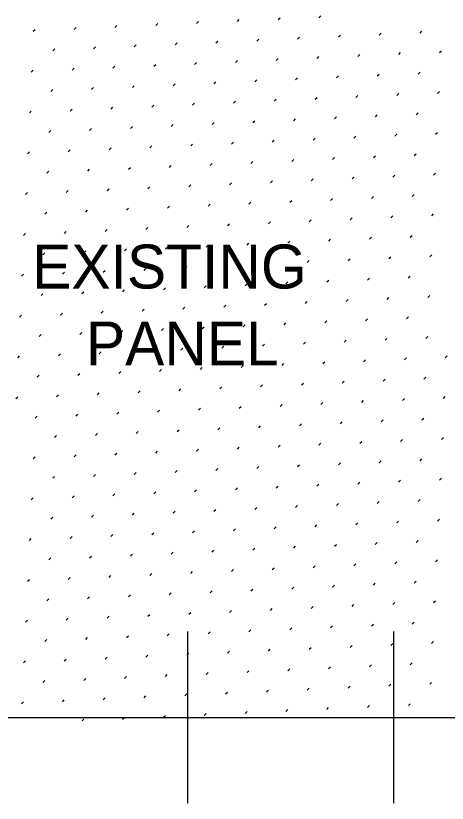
# Model space of a CAD drawing. Extents: x 49991.4 to 50021, y 49987.6 to 50011.4.
# Drawn here: x 50002.935 to 50003.72, y 49996.134 to 49997.567 of the extents above; entities that cross this region are included whole.
import ezdxf

# ---------------------------------------------------------------- set-up
doc = ezdxf.new("R2010")
doc.units = 0
for name, color, linetype in [('Level 1', 7, 'Continuous'), ('Level 10', 7, 'Continuous'), ('Level 2', 7, 'Continuous'), ('Level 4', 7, 'Continuous')]:
    doc.layers.add(name, color=color, linetype=linetype)

msp = doc.modelspace()

# ---------------------------------------------------------------- linework, layer by layer
at = {"layer": 'Level 1'}
msp.add_line((50002.3098, 49996.2901), (50007.9348, 49996.2901), dxfattribs=at)
at = {"layer": 'Level 10'}
for p, q in [((50003.4125, 49997.5595), (50003.416, 49997.5631)), ((50003.4867, 49997.5631), (50003.4903, 49997.5666)), ((50003.1155, 49997.5454), (50003.119, 49997.5489)), ((50003.1897, 49997.5489), (50003.1933, 49997.5524)), ((50003.264, 49997.5525), (50003.2675, 49997.556)), ((50003.3382, 49997.556), (50003.3418, 49997.5595)), ((50002.967, 49997.5383), (50002.9705, 49997.5418)), ((50003.0412, 49997.5418), (50003.0448, 49997.5454)), ((50003.5964, 49997.5313), (50003.5999, 49997.5348)), ((50003.6706, 49997.5348), (50003.6741, 49997.5383)), ((50003.2993, 49997.5171), (50003.3029, 49997.5206)), ((50003.3736, 49997.5206), (50003.3771, 49997.5242)), ((50003.4478, 49997.5242), (50003.4514, 49997.5277)), ((50003.5221, 49997.5277), (50003.5256, 49997.5313)), ((50003.0023, 49997.5029), (50003.0059, 49997.5065)), ((50003.0766, 49997.5065), (50003.0801, 49997.51)), ((50003.1508, 49997.51), (50003.1544, 49997.5136)), ((50003.2251, 49997.5136), (50003.2286, 49997.5171)), ((50003.4832, 49997.4888), (50003.4867, 49997.4924)), ((50003.5575, 49997.4924), (50003.561, 49997.4959)), ((50003.6317, 49997.4959), (50003.6352, 49997.4995)), ((50003.706, 49997.4995), (50003.7095, 49997.503)), ((50003.1862, 49997.4747), (50003.1897, 49997.4782)), ((50003.2604, 49997.4782), (50003.264, 49997.4817)), ((50003.3347, 49997.4817), (50003.3382, 49997.4853)), ((50003.409, 49997.4853), (50003.4125, 49997.4888)), ((50002.9634, 49997.464), (50002.967, 49997.4676)), ((50003.0377, 49997.4676), (50003.0412, 49997.4711)), ((50003.1119, 49997.4711), (50003.1155, 49997.4747)), ((50003.6671, 49997.4606), (50003.6706, 49997.4641)), ((50003.3701, 49997.4464), (50003.3736, 49997.4499)), ((50003.4443, 49997.4499), (50003.4478, 49997.4535)), ((50003.5186, 49997.4535), (50003.5221, 49997.457)), ((50003.5928, 49997.457), (50003.5963, 49997.4606)), ((50003.073, 49997.4322), (50003.0766, 49997.4358)), ((50003.1473, 49997.4358), (50003.1508, 49997.4393)), ((50003.2215, 49997.4393), (50003.2251, 49997.4428)), ((50003.2958, 49997.4428), (50003.2993, 49997.4464)), ((50002.9988, 49997.4287), (50003.0023, 49997.4322)), ((50003.5539, 49997.4181), (50003.5575, 49997.4217)), ((50003.6282, 49997.4217), (50003.6317, 49997.4252)), ((50003.7024, 49997.4252), (50003.706, 49997.4287)), ((50003.2569, 49997.404), (50003.2604, 49997.4075)), ((50003.3312, 49997.4075), (50003.3347, 49997.411)), ((50003.4054, 49997.411), (50003.4089, 49997.4146)), ((50003.4797, 49997.4146), (50003.4832, 49997.4181)), ((50002.9599, 49997.3898), (50002.9634, 49997.3933)), ((50003.0341, 49997.3933), (50003.0377, 49997.3969)), ((50003.1084, 49997.3969), (50003.1119, 49997.4004)), ((50003.1826, 49997.4004), (50003.1862, 49997.4039)), ((50003.3665, 49997.3721), (50003.37, 49997.3757)), ((50003.4408, 49997.3757), (50003.4443, 49997.3792)), ((50003.515, 49997.3792), (50003.5186, 49997.3828)), ((50003.5893, 49997.3828), (50003.5928, 49997.3863)), ((50003.6635, 49997.3863), (50003.6671, 49997.3898)), ((50003.0695, 49997.358), (50003.073, 49997.3615)), ((50003.1438, 49997.3615), (50003.1473, 49997.365)), ((50003.218, 49997.3651), (50003.2215, 49997.3686)), ((50003.2923, 49997.3686), (50003.2958, 49997.3721)), ((50002.9952, 49997.3544), (50002.9988, 49997.358)), ((50003.5504, 49997.3439), (50003.5539, 49997.3474)), ((50003.6246, 49997.3474), (50003.6282, 49997.3509)), ((50003.6989, 49997.351), (50003.7024, 49997.3545)), ((50003.2534, 49997.3297), (50003.2569, 49997.3332)), ((50003.3276, 49997.3332), (50003.3311, 49997.3368)), ((50003.4019, 49997.3368), (50003.4054, 49997.3403)), ((50003.4761, 49997.3403), (50003.4797, 49997.3439)), ((50002.9563, 49997.3155), (50002.9599, 49997.3191)), ((50003.0306, 49997.3191), (50003.0341, 49997.3226)), ((50003.1049, 49997.3226), (50003.1084, 49997.3261)), ((50003.1791, 49997.3262), (50003.1826, 49997.3297)), ((50003.4372, 49997.3014), (50003.4408, 49997.305)), ((50003.5115, 49997.305), (50003.515, 49997.3085)), ((50003.5857, 49997.3085), (50003.5893, 49997.312)), ((50003.66, 49997.3121), (50003.6635, 49997.3156)), ((50003.1402, 49997.2873), (50003.1437, 49997.2908)), ((50003.2145, 49997.2908), (50003.218, 49997.2943)), ((50003.2887, 49997.2943), (50003.2922, 49997.2979)), ((50003.363, 49997.2979), (50003.3665, 49997.3014)), ((50002.9917, 49997.2802), (50002.9952, 49997.2837)), ((50003.066, 49997.2837), (50003.0695, 49997.2872)), ((50003.6211, 49997.2732), (50003.6246, 49997.2767)), ((50003.6953, 49997.2767), (50003.6989, 49997.2802)), ((50003.3241, 49997.259), (50003.3276, 49997.2625)), ((50003.3983, 49997.2625), (50003.4019, 49997.2661)), ((50003.4726, 49997.2661), (50003.4761, 49997.2696)), ((50003.5468, 49997.2696), (50003.5504, 49997.2731)), ((50003.0271, 49997.2448), (50003.0306, 49997.2484)), ((50003.1013, 49997.2484), (50003.1048, 49997.2519)), ((50003.1756, 49997.2519), (50003.1791, 49997.2554)), ((50003.2498, 49997.2554), (50003.2534, 49997.259)), ((50002.9528, 49997.2413), (50002.9563, 49997.2448)), ((50003.5079, 49997.2307), (50003.5115, 49997.2343)), ((50003.5822, 49997.2343), (50003.5857, 49997.2378)), ((50003.6564, 49997.2378), (50003.66, 49997.2413)), ((50003.2109, 49997.2165), (50003.2145, 49997.2201)), ((50003.2852, 49997.2201), (50003.2887, 49997.2236)), ((50003.3594, 49997.2236), (50003.363, 49997.2272)), ((50003.4337, 49997.2272), (50003.4372, 49997.2307)), ((50002.9882, 49997.2059), (50002.9917, 49997.2095)), ((50003.0624, 49997.2095), (50003.0659, 49997.213)), ((50003.1367, 49997.213), (50003.1402, 49997.2165)), ((50003.6918, 49997.2024), (50003.6953, 49997.206)), ((50003.3948, 49997.1883), (50003.3983, 49997.1918)), ((50003.469, 49997.1918), (50003.4726, 49997.1954)), ((50003.5433, 49997.1954), (50003.5468, 49997.1989)), ((50003.6175, 49997.1989), (50003.6211, 49997.2024)), ((50003.0978, 49997.1741), (50003.1013, 49997.1776)), ((50003.172, 49997.1776), (50003.1756, 49997.1812)), ((50003.2463, 49997.1812), (50003.2498, 49997.1847)), ((50003.3205, 49997.1847), (50003.3241, 49997.1883)), ((50002.9493, 49997.167), (50002.9528, 49997.1706)), ((50003.0235, 49997.1706), (50003.027, 49997.1741)), ((50003.5786, 49997.16), (50003.5822, 49997.1635)), ((50003.6529, 49997.1635), (50003.6564, 49997.1671)), ((50003.2816, 49997.1458), (50003.2852, 49997.1494)), ((50003.3559, 49997.1494), (50003.3594, 49997.1529)), ((50003.4301, 49997.1529), (50003.4337, 49997.1565)), ((50003.5044, 49997.1565), (50003.5079, 49997.16)), ((50002.9846, 49997.1317), (50002.9882, 49997.1352)), ((50003.0589, 49997.1352), (50003.0624, 49997.1387)), ((50003.1331, 49997.1387), (50003.1367, 49997.1423)), ((50003.2074, 49997.1423), (50003.2109, 49997.1458)), ((50003.4655, 49997.1176), (50003.469, 49997.1211)), ((50003.5397, 49997.1211), (50003.5433, 49997.1246)), ((50003.614, 49997.1247), (50003.6175, 49997.1282)), ((50003.6883, 49997.1282), (50003.6918, 49997.1317)), ((50003.1685, 49997.1034), (50003.172, 49997.1069)), ((50003.2427, 49997.1069), (50003.2463, 49997.1105)), ((50003.317, 49997.1105), (50003.3205, 49997.114)), ((50003.3912, 49997.114), (50003.3948, 49997.1176)), ((50002.9457, 49997.0928), (50002.9493, 49997.0963)), ((50003.02, 49997.0963), (50003.0235, 49997.0998)), ((50003.0942, 49997.0999), (50003.0978, 49997.1034)), ((50003.5751, 49997.0858), (50003.5786, 49997.0893)), ((50003.6494, 49997.0893), (50003.6529, 49997.0928)), ((50003.2781, 49997.0716), (50003.2816, 49997.0751)), ((50003.3523, 49997.0751), (50003.3559, 49997.0787)), ((50003.4266, 49997.0787), (50003.4301, 49997.0822)), ((50003.5008, 49997.0822), (50003.5044, 49997.0857)), ((50002.9811, 49997.0574), (50002.9846, 49997.0609)), ((50003.0553, 49997.061), (50003.0589, 49997.0645)), ((50003.1296, 49997.0645), (50003.1331, 49997.068)), ((50003.2038, 49997.068), (50003.2074, 49997.0716)), ((50003.4619, 49997.0433), (50003.4655, 49997.0468)), ((50003.5362, 49997.0469), (50003.5397, 49997.0504)), ((50003.6105, 49997.0504), (50003.614, 49997.0539)), ((50003.6847, 49997.0539), (50003.6882, 49997.0575)), ((50003.1649, 49997.0291), (50003.1685, 49997.0327)), ((50003.2392, 49997.0327), (50003.2427, 49997.0362)), ((50003.3134, 49997.0362), (50003.317, 49997.0398)), ((50003.3877, 49997.0398), (50003.3912, 49997.0433)), ((50002.9422, 49997.0185), (50002.9457, 49997.022)), ((50003.0164, 49997.0221), (50003.02, 49997.0256)), ((50003.0907, 49997.0256), (50003.0942, 49997.0291)), ((50003.6458, 49997.015), (50003.6493, 49997.0186)), ((50003.3488, 49997.0009), (50003.3523, 49997.0044)), ((50003.4231, 49997.0044), (50003.4266, 49997.0079)), ((50003.4973, 49997.008), (50003.5008, 49997.0115)), ((50003.5716, 49997.0115), (50003.5751, 49997.015)), ((50003.0518, 49996.9867), (50003.0553, 49996.9902)), ((50003.126, 49996.9902), (50003.1296, 49996.9938)), ((50003.2003, 49996.9938), (50003.2038, 49996.9973)), ((50003.2745, 49996.9973), (50003.2781, 49997.0009)), ((50002.9775, 49996.9832), (50002.9811, 49996.9867)), ((50003.5327, 49996.9726), (50003.5362, 49996.9761)), ((50003.6069, 49996.9761), (50003.6104, 49996.9797)), ((50003.6812, 49996.9797), (50003.6847, 49996.9832)), ((50003.2356, 49996.9584), (50003.2392, 49996.962)), ((50003.3099, 49996.962), (50003.3134, 49996.9655)), ((50003.3842, 49996.9655), (50003.3877, 49996.9691)), ((50003.4584, 49996.9691), (50003.4619, 49996.9726)), ((50002.9386, 49996.9443), (50002.9422, 49996.9478)), ((50003.0129, 49996.9478), (50003.0164, 49996.9513)), ((50003.0871, 49996.9513), (50003.0907, 49996.9549)), ((50003.1614, 49996.9549), (50003.1649, 49996.9584)), ((50003.7165, 49996.9443), (50003.7201, 49996.9479)), ((50003.4195, 49996.9302), (50003.423, 49996.9337)), ((50003.4938, 49996.9337), (50003.4973, 49996.9372)), ((50003.568, 49996.9372), (50003.5715, 49996.9408)), ((50003.6423, 49996.9408), (50003.6458, 49996.9443)), ((50003.1225, 49996.916), (50003.126, 49996.9195)), ((50003.1967, 49996.9195), (50003.2003, 49996.9231)), ((50003.271, 49996.9231), (50003.2745, 49996.9266)), ((50003.3453, 49996.9266), (50003.3488, 49996.9302)), ((50002.974, 49996.9089), (50002.9775, 49996.9124)), ((50003.0482, 49996.9124), (50003.0518, 49996.916)), ((50003.6034, 49996.9019), (50003.6069, 49996.9054)), ((50003.6776, 49996.9054), (50003.6812, 49996.909)), ((50003.3064, 49996.8877), (50003.3099, 49996.8913)), ((50003.3806, 49996.8913), (50003.3841, 49996.8948)), ((50003.4549, 49996.8948), (50003.4584, 49996.8983)), ((50003.5291, 49996.8983), (50003.5327, 49996.9019)), ((50003.0093, 49996.8735), (50003.0129, 49996.8771)), ((50003.0836, 49996.8771), (50003.0871, 49996.8806)), ((50003.1579, 49996.8806), (50003.1614, 49996.8842)), ((50003.2321, 49996.8842), (50003.2356, 49996.8877)), ((50002.9351, 49996.87), (50002.9386, 49996.8735)), ((50003.4902, 49996.8594), (50003.4938, 49996.863)), ((50003.5645, 49996.863), (50003.568, 49996.8665)), ((50003.6387, 49996.8665), (50003.6423, 49996.8701)), ((50003.713, 49996.8701), (50003.7165, 49996.8736)), ((50003.1932, 49996.8453), (50003.1967, 49996.8488)), ((50003.2675, 49996.8488), (50003.271, 49996.8524)), ((50003.3417, 49996.8524), (50003.3452, 49996.8559)), ((50003.416, 49996.8559), (50003.4195, 49996.8594)), ((50002.9704, 49996.8347), (50002.974, 49996.8382)), ((50003.0447, 49996.8382), (50003.0482, 49996.8417)), ((50003.119, 49996.8417), (50003.1225, 49996.8453)), ((50003.6741, 49996.8312), (50003.6776, 49996.8347)), ((50003.3028, 49996.8135), (50003.3063, 49996.817)), ((50003.3771, 49996.817), (50003.3806, 49996.8205)), ((50003.4513, 49996.8206), (50003.4549, 49996.8241)), ((50003.5256, 49996.8241), (50003.5291, 49996.8276)), ((50003.5998, 49996.8276), (50003.6034, 49996.8312)), ((50003.0058, 49996.7993), (50003.0093, 49996.8028)), ((50003.0801, 49996.8028), (50003.0836, 49996.8064)), ((50003.1543, 49996.8064), (50003.1578, 49996.8099)), ((50003.2286, 49996.8099), (50003.2321, 49996.8135)), ((50003.4867, 49996.7852), (50003.4902, 49996.7887)), ((50003.5609, 49996.7887), (50003.5645, 49996.7923)), ((50003.6352, 49996.7923), (50003.6387, 49996.7958)), ((50003.7094, 49996.7958), (50003.713, 49996.7994)), ((50003.1897, 49996.771), (50003.1932, 49996.7746)), ((50003.2639, 49996.7746), (50003.2675, 49996.7781)), ((50003.3382, 49996.7781), (50003.3417, 49996.7816)), ((50003.4124, 49996.7817), (50003.416, 49996.7852)), ((50002.9669, 49996.7604), (50002.9704, 49996.7639)), ((50003.0412, 49996.7639), (50003.0447, 49996.7675)), ((50003.1154, 49996.7675), (50003.1189, 49996.771)), ((50003.6705, 49996.7569), (50003.6741, 49996.7605)), ((50003.3735, 49996.7428), (50003.3771, 49996.7463)), ((50003.4478, 49996.7463), (50003.4513, 49996.7498)), ((50003.522, 49996.7498), (50003.5256, 49996.7534)), ((50003.5963, 49996.7534), (50003.5998, 49996.7569)), ((50003.0765, 49996.7286), (50003.08, 49996.7321)), ((50003.1508, 49996.7321), (50003.1543, 49996.7357)), ((50003.225, 49996.7357), (50003.2286, 49996.7392)), ((50003.2993, 49996.7392), (50003.3028, 49996.7427)), ((50003.0023, 49996.725), (50003.0058, 49996.7286)), ((50003.5574, 49996.7145), (50003.5609, 49996.718)), ((50003.6316, 49996.718), (50003.6352, 49996.7216)), ((50003.7059, 49996.7216), (50003.7094, 49996.7251)), ((50003.2604, 49996.7003), (50003.2639, 49996.7039)), ((50003.3346, 49996.7039), (50003.3382, 49996.7074)), ((50003.4089, 49996.7074), (50003.4124, 49996.7109)), ((50003.4831, 49996.7109), (50003.4867, 49996.7145)), ((50002.9634, 49996.6861), (50002.9669, 49996.6897)), ((50003.0376, 49996.6897), (50003.0411, 49996.6932)), ((50003.1119, 49996.6932), (50003.1154, 49996.6968)), ((50003.1861, 49996.6968), (50003.1897, 49996.7003)), ((50003.4442, 49996.672), (50003.4478, 49996.6756)), ((50003.5185, 49996.6756), (50003.522, 49996.6791)), ((50003.5927, 49996.6791), (50003.5963, 49996.6827)), ((50003.667, 49996.6827), (50003.6705, 49996.6862)), ((50003.1472, 49996.6579), (50003.1508, 49996.6614)), ((50003.2215, 49996.6614), (50003.225, 49996.665)), ((50003.2957, 49996.665), (50003.2993, 49996.6685)), ((50003.37, 49996.6685), (50003.3735, 49996.672)), ((50002.9987, 49996.6508), (50003.0023, 49996.6543)), ((50003.073, 49996.6543), (50003.0765, 49996.6579)), ((50003.6281, 49996.6438), (50003.6316, 49996.6473)), ((50003.7024, 49996.6473), (50003.7059, 49996.6509)), ((50003.3311, 49996.6296), (50003.3346, 49996.6331)), ((50003.4053, 49996.6331), (50003.4089, 49996.6367)), ((50003.4796, 49996.6367), (50003.4831, 49996.6402)), ((50003.5538, 49996.6402), (50003.5574, 49996.6438)), ((50003.0341, 49996.6154), (50003.0376, 49996.619)), ((50003.1083, 49996.619), (50003.1119, 49996.6225)), ((50003.1826, 49996.6225), (50003.1861, 49996.6261)), ((50003.2568, 49996.6261), (50003.2604, 49996.6296)), ((50002.9598, 49996.6119), (50002.9634, 49996.6154)), ((50003.5149, 49996.6013), (50003.5185, 49996.6049)), ((50003.5892, 49996.6049), (50003.5927, 49996.6084)), ((50003.6635, 49996.6084), (50003.667, 49996.612)), ((50003.2179, 49996.5872), (50003.2215, 49996.5907)), ((50003.2922, 49996.5907), (50003.2957, 49996.5942)), ((50003.3664, 49996.5942), (50003.37, 49996.5978)), ((50003.4407, 49996.5978), (50003.4442, 49996.6013)), ((50002.9952, 49996.5765), (50002.9987, 49996.5801)), ((50003.0694, 49996.5801), (50003.073, 49996.5836)), ((50003.1437, 49996.5836), (50003.1472, 49996.5872)), ((50003.6988, 49996.5731), (50003.7023, 49996.5766)), ((50003.4018, 49996.5589), (50003.4053, 49996.5624)), ((50003.476, 49996.5624), (50003.4796, 49996.566)), ((50003.5503, 49996.566), (50003.5538, 49996.5695)), ((50003.6246, 49996.5695), (50003.6281, 49996.5731)), ((50003.0305, 49996.5412), (50003.0341, 49996.5447)), ((50003.1048, 49996.5447), (50003.1083, 49996.5483)), ((50003.179, 49996.5483), (50003.1826, 49996.5518)), ((50003.2533, 49996.5518), (50003.2568, 49996.5553)), ((50003.3275, 49996.5554), (50003.3311, 49996.5589)), ((50002.9563, 49996.5376), (50002.9598, 49996.5412)), ((50003.5114, 49996.5271), (50003.5149, 49996.5306)), ((50003.5857, 49996.5306), (50003.5892, 49996.5342)), ((50003.6599, 49996.5342), (50003.6634, 49996.5377)), ((50003.2144, 49996.5129), (50003.2179, 49996.5164)), ((50003.2886, 49996.5165), (50003.2922, 49996.52)), ((50003.3629, 49996.52), (50003.3664, 49996.5235)), ((50003.4372, 49996.5235), (50003.4407, 49996.5271)), ((50002.9916, 49996.5023), (50002.9952, 49996.5058)), ((50003.0659, 49996.5058), (50003.0694, 49996.5094)), ((50003.1401, 49996.5094), (50003.1437, 49996.5129)), ((50003.6953, 49996.4988), (50003.6988, 49996.5023)), ((50003.3983, 49996.4846), (50003.4018, 49996.4882)), ((50003.4725, 49996.4882), (50003.476, 49996.4917)), ((50003.5468, 49996.4917), (50003.5503, 49996.4953)), ((50003.621, 49996.4953), (50003.6245, 49996.4988)), ((50003.1012, 49996.4705), (50003.1048, 49996.474)), ((50003.1755, 49996.474), (50003.179, 49996.4775)), ((50003.2497, 49996.4776), (50003.2533, 49996.4811)), ((50003.324, 49996.4811), (50003.3275, 49996.4846)), ((50002.9527, 49996.4634), (50002.9563, 49996.4669)), ((50003.027, 49996.4669), (50003.0305, 49996.4705)), ((50003.5821, 49996.4564), (50003.5856, 49996.4599)), ((50003.6564, 49996.4599), (50003.6599, 49996.4634)), ((50003.2851, 49996.4422), (50003.2886, 49996.4457)), ((50003.3594, 49996.4457), (50003.3629, 49996.4493)), ((50003.4336, 49996.4493), (50003.4371, 49996.4528)), ((50003.5079, 49996.4528), (50003.5114, 49996.4564)), ((50002.9881, 49996.428), (50002.9916, 49996.4316)), ((50003.0623, 49996.4316), (50003.0659, 49996.4351)), ((50003.1366, 49996.4351), (50003.1401, 49996.4387)), ((50003.2108, 49996.4387), (50003.2144, 49996.4422)), ((50003.469, 49996.4139), (50003.4725, 49996.4175)), ((50003.5432, 49996.4175), (50003.5468, 49996.421)), ((50003.6175, 49996.421), (50003.621, 49996.4246)), ((50003.6917, 49996.4246), (50003.6953, 49996.4281)), ((50003.1719, 49996.3998), (50003.1755, 49996.4033)), ((50003.2462, 49996.4033), (50003.2497, 49996.4068)), ((50003.3205, 49996.4068), (50003.324, 49996.4104)), ((50003.3947, 49996.4104), (50003.3982, 49996.4139)), ((50002.9492, 49996.3891), (50002.9527, 49996.3927)), ((50003.0234, 49996.3927), (50003.027, 49996.3962)), ((50003.0977, 49996.3962), (50003.1012, 49996.3998)), ((50003.6528, 49996.3857), (50003.6564, 49996.3892)), ((50003.3558, 49996.3715), (50003.3593, 49996.375)), ((50003.4301, 49996.375), (50003.4336, 49996.3786)), ((50003.5043, 49996.3786), (50003.5079, 49996.3821)), ((50003.5786, 49996.3821), (50003.5821, 49996.3857)), ((50003.0588, 49996.3573), (50003.0623, 49996.3609)), ((50003.1331, 49996.3609), (50003.1366, 49996.3644)), ((50003.2073, 49996.3644), (50003.2108, 49996.3679)), ((50003.2816, 49996.3679), (50003.2851, 49996.3715)), ((50002.9845, 49996.3538), (50002.9881, 49996.3573)), ((50003.5397, 49996.3432), (50003.5432, 49996.3468)), ((50003.6139, 49996.3468), (50003.6175, 49996.3503)), ((50003.6882, 49996.3503), (50003.6917, 49996.3538)), ((50003.2427, 49996.329), (50003.2462, 49996.3326)), ((50003.3169, 49996.3326), (50003.3204, 49996.3361)), ((50003.3912, 49996.3361), (50003.3947, 49996.3397)), ((50003.4654, 49996.3397), (50003.469, 49996.3432)), ((50002.9456, 49996.3149), (50002.9492, 49996.3184)), ((50003.0199, 49996.3184), (50003.0234, 49996.322)), ((50003.0942, 49996.322), (50003.0977, 49996.3255)), ((50003.1684, 49996.3255), (50003.1719, 49996.329)), ((50003.4265, 49996.3008), (50003.4301, 49996.3043)), ((50003.5008, 49996.3043), (50003.5043, 49996.3079)), ((50003.575, 49996.3079), (50003.5786, 49996.3114)), ((50003.6493, 49996.3114), (50003.6528, 49996.3149)), ((50003.1295, 49996.2866), (50003.133, 49996.2901)), ((50003.2038, 49996.2902), (50003.2073, 49996.2937)), ((50003.278, 49996.2937), (50003.2816, 49996.2972)), ((50003.3523, 49996.2972), (50003.3558, 49996.3008)), ((50003.056, 49996.2838), (50003.0588, 49996.2866))]:
    msp.add_line(p, q, dxfattribs=at)
at = {"layer": 'Level 4'}
for p, q in [((50003.2473, 49996.4463), (50003.2473, 49996.1338)), ((50003.6223, 49996.4463), (50003.6223, 49996.1338))]:
    msp.add_line(p, q, dxfattribs=at)

# ---------------------------------------------------------------- texts
at = {"layer": 'Level 2'}
for s, p in [('EXISTING', (50002.9649, 49997.0703)), ('PANEL', (50003.0627, 49996.9303))]:
    msp.add_text(s, height=0.08, dxfattribs=at).set_placement(p)

doc.saveas('drawing.dxf')
